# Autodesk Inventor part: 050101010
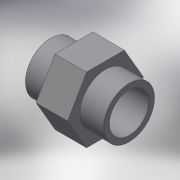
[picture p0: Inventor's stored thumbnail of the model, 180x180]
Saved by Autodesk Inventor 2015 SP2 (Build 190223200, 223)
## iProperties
Created: 2017-10
Part Number: 050101010
Material: Generic
Description: PLASSON THREADED SOCKET PVC 1"
Document SubType Name: Modeling
Designer: KIM
Density: 1 g/cm^3
Appearance: Default
Author: KIM
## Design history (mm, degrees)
derived "050101.ipt"
feature "Solid1::050101.ipt"
tag "TaggingFeature1"
body "Solid1"
other parameters: "d0" = 45, "d1" = 30.291, "d2" = 45, "d3" = 30.291, "d4" = 27.2619, "d7" = 39.3783, "d8" = 39.3783, "d10" = 14, "d13" = 0, "d14" = 0.30291, "d15" = 12, "G_" = 30.291, "C_" = 45, "B_" = 12, "H_" = 45
